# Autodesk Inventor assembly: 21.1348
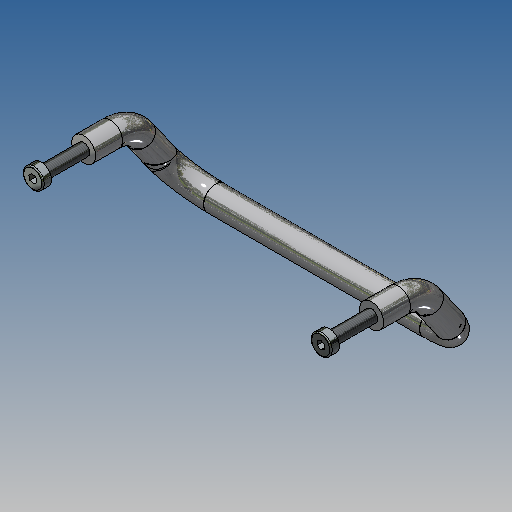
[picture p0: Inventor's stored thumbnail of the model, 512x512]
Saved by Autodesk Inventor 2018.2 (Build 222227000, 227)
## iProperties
Created: 2007-02
Part Number: 21.1348
Document SubType Name: Assembly
Designer: Andy Moles
Description: HANDLE AL ANGLED
Mass: 59.087 g
Surface Area: 93.6313 cm^2
Volume: 18.5372 cm^3
Density: 3.18748 g/cm^3
Author: Andy Moles
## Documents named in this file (3)
- Y:\INVENTOR LIBRARIES\PARTS LIBRARY\HANDLES LOCKS STOPS\21.1348 HANDLE AL ANGLED.iam
- Y:\INVENTOR LIBRARIES\PARTS LIBRARY\HANDLES LOCKS STOPS\SUBCOMPONENTS\21.1348 HANDLE AL ANGLED.ipt
- Y:\INVENTOR LIBRARIES\PARTS LIBRARY\FASTENING ELEMENTS\SCREWS CAP\21.1224 M5X25.ipt
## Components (3 placed, 2 different names)
1. 21.1348 HANDLE AL ANGLED:1 — Flush:1, Mate:1, Mate:2, Mate:5, Mate:6, Mate:7
2. 21.1224  M5 x 25:1 — Mate:1, Mate:6
3. 21.1224  M5 x 25:2 — Mate:2, Mate:7
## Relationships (6: Mate 5, Flush 1)
- Flush:1: 21.1348 HANDLE AL ANGLED:1
- Mate:1: 21.1348 HANDLE AL ANGLED:1 ↔ 21.1224  M5 x 25:1
- Mate:2: 21.1348 HANDLE AL ANGLED:1 ↔ 21.1224  M5 x 25:2
- Mate:5: 21.1348 HANDLE AL ANGLED:1
- Mate:6: 21.1348 HANDLE AL ANGLED:1 ↔ 21.1224  M5 x 25:1
- Mate:7: 21.1348 HANDLE AL ANGLED:1 ↔ 21.1224  M5 x 25:2
